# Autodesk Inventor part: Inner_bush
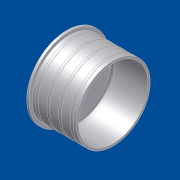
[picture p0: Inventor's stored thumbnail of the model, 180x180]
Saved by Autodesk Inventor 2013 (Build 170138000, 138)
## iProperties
Shininess: 69.0
Length Units: 11269
Angle Units: 11279
Time Units: 11290
Mass Units: 11283
Length Display Precision: 3
Angle Display Precision: 2
Created: 2001-04
Part Number: Inner_bush
Material: Standard
Document SubType Name: Modellieren
Designer: dl
Density: 1 g/cm^3
Density: 0.0
Volumn: 0.0
Area: 0.0
PropertySet Name: Model Information
Control State: 0
Master: False
Checked Out: False
Author: dl
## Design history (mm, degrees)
body "Solid1"
revolve "Revolution1" stored, may be unused: angle "d5" = 90 deg
revolve "Revolution2" stored, may be unused: angle "d9" = 90 deg
pattern_linear "Rectangular Pattern1" dims "d12" = 5
sketch "Sketch3"
  geometry: C1 r 15.9 at (0, 0) reference; 1 further point
  constraints: 1 coincident
hole "Hole1" sketch "Sketch3" diameter "d13" = 10; stored, may be unused: countersink angle "d17" = 60 deg, drill point angle "d19" = 118 deg; dims "d14" = 6, "d15" = 29.8, "d16" = 15.2, "d18" = 8
fillet "Fillet1" dims "d20" = 1
sketch "Sketch1"
  geometry: L1 (0, 0)-(0, 17.25); L2 (0, 17.25)-(1, 17.25); L3 (1, 17.25)-(1, 15.9); L4 (1, 15.9)-(20, 15.9); L5 (20, 15.9)-(20, 0); L6 (20, 0)-(0, 0)
  constraints: 12 end point, 4 parallel, 1 perpendicular, 1 vertical
  dimensions: "d1" = 19 distance of L3.end L4.end; "d2" = 20 distance of L5.end L1.start; "d3" = 15.9 distance of L4.end L5.end; "d4" = 17.25 distance of L1.start L1.end
sketch "Sketch2"
  geometry: L1 (0, -17.25)-(0, 17.25) reference; L2 (0, 0)-(27.932, 0); L3 (20, -15.9)-(20, 15.9) reference; C1 r 1 at (18, 16.7)
  constraints: 2 end point, 1 centre point, 1 midpoint, 1 perpendicular
  dimensions: "d6" = 2 diameter of C1; "d7" = 16.7 distance from line of C1.centre L2; "d8" = 2 distance from line of L3 C1.centre
